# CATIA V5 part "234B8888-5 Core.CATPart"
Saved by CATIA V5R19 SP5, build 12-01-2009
Part number: 234B8888-5 Core
Publications: "Top of Core IML"
Material "Sponge": density 10 kg/m3
Bounding box of the stored display mesh (mm): x 31577.01 to 31897.879, y -11300.23 to -11187.942, z 5317.488 to 5442.413
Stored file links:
  C:\Users\rem1927\Desktop\Current Explicit Composite Demo\234B8888-5 Core.CATPart
  C:\Users\rem1927\Desktop\Current Explicit Composite Demo\234B5678-1 Composite Product.CATProduct
  C:\Program Files\Dassault Systemes\B23SP2PRALL\win_b64\startup\materials\Catalog.CATMaterial
  C:\Program Files\Dassault Systemes\B23SP2PRALL\win_b64\startup\materials\sponge.jpg
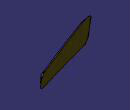
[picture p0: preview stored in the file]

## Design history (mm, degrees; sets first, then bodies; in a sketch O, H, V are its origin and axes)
Set1 "Construction"
  Offset1: Offset DatumSurface1, Length 0
  Intersect1: ToIntersect1 Offset1, ToIntersect2 DatumSurface2
  Intersect2: ToIntersect1 Offset1, ToIntersect2 DatumSurface3
  Extract1: ExtractElem edge [face of Offset1 | face of Offset1]
  Extract2: ExtractElem edge [face of Offset1 | face of Offset1]
  CurvePar1: Offset Extract2, Support Offset1, Offset2 0, Offset1 12.7
  CurvePar2: Offset Extract1, Support Offset1, Offset2 0, Offset1 12.7
  DatumCurve1
  DatumCurve2
  CurvePar3: Offset DatumCurve1, Support Offset1, Offset2 0, Offset1 12.7
  CurvePar4: Offset DatumCurve2, Support Offset1, Offset2 0, Offset1 12.7
  Corner1: Element1 CurvePar2, Element2 CurvePar3, Support Offset1, Radius 25.4
  Corner2: Element1 Corner1, Element2 CurvePar4, Radius 25.4
  Corner3: Element1 Corner2, Element2 CurvePar1, Radius 25.4
  Corner4: Element1 Corner3, Element2 CurvePar1, Radius 25.4
  Split1: ToCut CurvePar1, Cutting Corner4
  Join1: Elements (Corner4; Split1)
  Sweep1: type Segment, GuideCrv Join1, GuideSurf Offset1, Length1 26.67, Length2 0, Angle 30
  Split2: ToCut Offset1, Cutting Join1
  Point1: type OnCurve, Support Join1, RefPoint vertex [face of CurvePar1 | face of Corner4], Ratio 0.56
  Line1: type Angle, RefPoint Point1, Curve DatumCurve1, Start 50.8, End 279.4, Angle 90
Set2 "Core Ribbon Direction"
  Extrude1: Element1 Line1, Lim1 25.4, Lim2 0, Direction face of ThickSurface1
Set3
  DatumSurface1 "Core Layup Surface": linked copy from another document
  DatumSurface2 "aft_trim_surface": linked copy from another document
  DatumSurface3 "fwd_trim_surface": linked copy from another document
Set4
  Extract3: ExtractElem face of Split3
  Extract4: ExtractElem face of ThickSurface1
  Join2: Elements (Extract4; Extract3)
  Fillet1 "Top of Core IML": type BiTangent, Element1 Join2, Element2 {split ToCut Offset1, Cutting Join1}, Radius 6.35
Body1 "Core - 234B8888-5" (main body), material "Sponge"
  ThickSurface1: BotOffset 0, Surface Split2, TopOffset 12.7
  Split3: SplitPlane Sweep1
